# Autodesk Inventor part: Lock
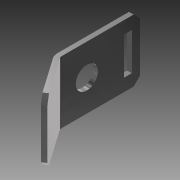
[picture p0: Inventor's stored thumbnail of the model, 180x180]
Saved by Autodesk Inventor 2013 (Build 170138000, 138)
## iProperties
Created: 2009-03
Part Number: Lock
Document SubType Name: Modeling
Designer: tangg
Density: 7.84 g/cm^3
Material: Steel, High Strength Low Alloy
Mass: 9.0689 g
Surface Area: 17.998 cm^2
Volume: 1.15675 cm^3
Author: tangg
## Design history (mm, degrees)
sketch "Sketch1"
  geometry: L1 (0, 17)-(1.5, 17); L2 (1.5, 17)-(1.5, 0); L3 (1.5, -25)-(0, -25); L4 (0, -25)-(0, 0); L5 (0, 0)-(1.5, 0); L6 (0, 0)-(0, 17); L7 (1.5, 0)-(1.5, -25); 1 further point
  constraints: 14 end point, 5 parallel, 2 perpendicular, 1 coincident, 1 horizontal
  dimensions: "d6" = 1.5 distance between parallel lines of L2 L4; "d8" = 17 distance from line of point (0, 0) L1; "d9" = 25 distance between parallel lines of L5 L3
extrude "Extrusion1" new body sketch "Sketch1" stored distance "d0" = 20; taper "d1" = 0 deg
sketch "Sketch2"
  geometry: L1 (4, 39.414)-(16, 39.414); L2 (16, 39.414)-(16, 36.914); L3 (16, 36.914)-(4, 36.914); L4 (4, 36.914)-(4, 39.414); L5 (15, 39.414)-(5, 39.414) reference; C1 r 3.568 at (10, 25); 2 further points
  constraints: 8 end point, 2 parallel, 1 centre point, 1 coincident, 1 collinear, 1 horizontal, 1 midpoint, 1 perpendicular, 1 vertical alignment
  dimensions: "d4" = 12 distance between parallel lines of L2 L4; "d5" = 2.5 distance between parallel lines of L3 L1
extrude "Extrusion2" cut sketch "Sketch2" stored distance "d2" = 20; taper "d3" = 0 deg
sketch "Sketch3"
  geometry: L1 (0, 42)-(0, 0) reference; L2 (20, 0)-(20, 42) reference; L3 (0, 17)-(20, 17); A1 r 3.568 centre (10, 25) between (6.957, 23.136) and (13.043, 23.136) reference
  constraints: 2 end point, 2 point on line, 1 perpendicular
  dimensions: "d10" = 8 distance from line of L3 A1.centre
feature "Bend Part1" sketch "Sketch3" dims "d11" = 2, "d12" = 35 deg
chamfer "Chamfer1" distance "d13" = 2; stored, may be unused: second distance "d14" = 2, angle "d15" = 45 deg
body "Solid1"
node "Reference2"
